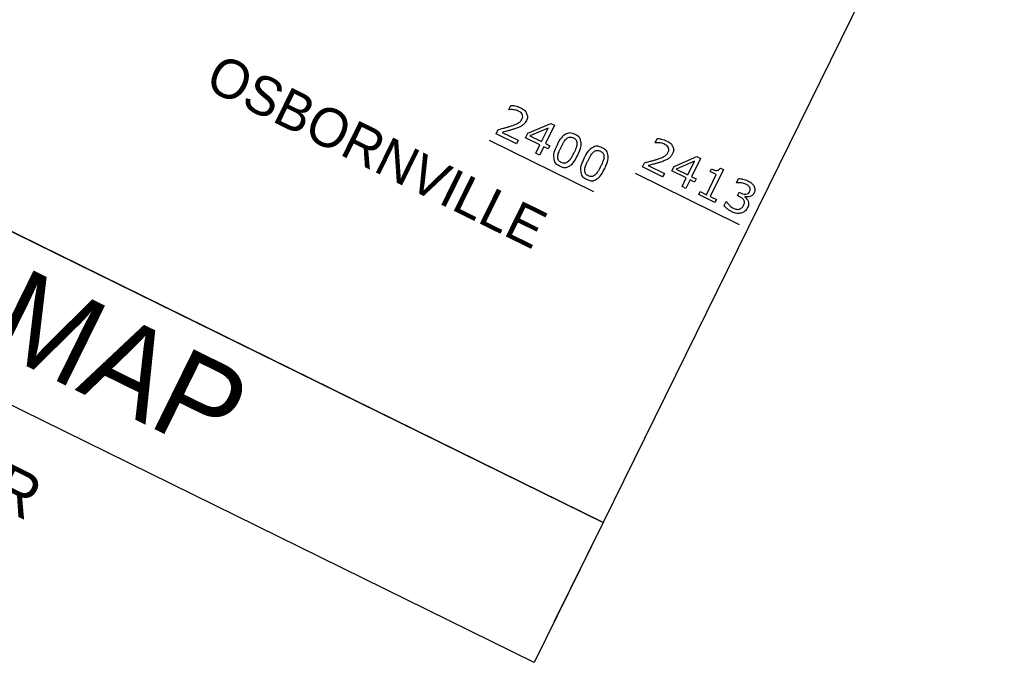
# Model space of a CAD drawing. Extents: x 1428128 to 1430390, y 857947 to 859822.
# Drawn here: x 1429086 to 1429305.6, y 859073.3 to 859217.9 of the extents above; entities that cross this region are included whole.
import ezdxf

# ---------------------------------------------------------------- set-up
doc = ezdxf.new("R2010")
doc.units = 0
for name, color, linetype in [('Old_Level_1', 7, 'Continuous'), ('Sheet Data Field CELL', 7, 'Continuous'), ('Sheet Title CELL', 7, 'Continuous')]:
    doc.layers.add(name, color=color, linetype=linetype)

msp = doc.modelspace()

# ---------------------------------------------------------------- linework, layer by layer
at = {"layer": 'Old_Level_1'}
for p, q in [((1429191.52, 859190.73), (1429214.98, 859179.19)), ((1429224.37, 859183.28), (1429247.75, 859171.78))]:
    msp.add_line(p, q, dxfattribs=at)
for points in [[(1429196.04, 859197.57), (1429196, 859197.59), (1429196.46, 859198.54)], [(1429204.83, 859188.76), (1429203.83, 859189.26), (1429202.9, 859187.36), (1429202.03, 859187.79), (1429202.96, 859189.68), (1429199.74, 859191.27), (1429200.25, 859192.31), (1429205.38, 859194.5), (1429206.21, 859194.09), (1429204.19, 859189.98), (1429205.19, 859189.49), (1429204.83, 859188.76)], [(1429203.32, 859190.41), (1429204.82, 859193.45), (1429200.71, 859191.69), (1429203.32, 859190.41)], [(1429197.68, 859189.93), (1429193.12, 859192.17), (1429193.59, 859193.12)], [(1429194.44, 859192.49), (1429198.07, 859190.71), (1429197.68, 859189.93)], [(1429228.9, 859190.12), (1429228.85, 859190.14), (1429229.32, 859191.09)], [(1429237.69, 859181.31), (1429236.69, 859181.8), (1429235.76, 859179.9), (1429234.89, 859180.33), (1429235.82, 859182.23), (1429232.6, 859183.81), (1429233.11, 859184.85), (1429238.24, 859187.04), (1429239.07, 859186.63), (1429237.05, 859182.52), (1429238.05, 859182.03), (1429237.69, 859181.31)], [(1429230.54, 859182.47), (1429225.98, 859184.71), (1429226.45, 859185.67)], [(1429227.3, 859185.03), (1429230.92, 859183.25), (1429230.54, 859182.47)], [(1429236.18, 859182.95), (1429237.67, 859185.99), (1429233.57, 859184.24), (1429236.18, 859182.95)], [(1429243.53, 859184.47), (1429244.23, 859184.12), (1429241.25, 859178.06), (1429242.62, 859177.38), (1429242.28, 859176.69)], [(1429242.28, 859176.69), (1429238.64, 859178.49), (1429238.98, 859179.17), (1429240.38, 859178.48), (1429242.6, 859182.99), (1429241.2, 859183.68), (1429241.5, 859184.3)], [(1429247.14, 859181.14), (1429247.1, 859181.16), (1429247.56, 859182.1)], [(1429247.77, 859178.07), (1429247.37, 859178.27), (1429247.73, 859179.01), (1429248.05, 859178.86)], [(1429249, 859178.04), (1429248.97, 859177.97)], [(1429244.34, 859176.03), (1429244.8, 859176.98), (1429244.87, 859176.94)]]:
    msp.add_lwpolyline(points, dxfattribs=at)
for points in [[(1429193.59, 859193.12), (1429194.27, 859193.29), (1429194.95, 859193.47), (1429195.62, 859193.64), (1429196.23, 859193.84), (1429197.52, 859194.25), (1429198.08, 859194.59), (1429198.65, 859194.92), (1429198.93, 859195.5), (1429199.19, 859196.02), (1429198.99, 859196.49), (1429198.78, 859196.95), (1429198.16, 859197.26), (1429197.75, 859197.46), (1429197.2, 859197.55), (1429196.65, 859197.64), (1429196.04, 859197.57)], [(1429196.46, 859198.54), (1429196.86, 859198.54), (1429197.46, 859198.41), (1429198.06, 859198.28), (1429198.57, 859198.03), (1429199.6, 859197.52), (1429199.95, 859196.73), (1429200.29, 859195.94), (1429199.87, 859195.09), (1429199.68, 859194.7), (1429199.42, 859194.42), (1429199.16, 859194.14), (1429198.82, 859193.93), (1429198.51, 859193.74), (1429198.14, 859193.58), (1429197.77, 859193.43), (1429197.26, 859193.27), (1429196.55, 859193.03), (1429195.81, 859192.84), (1429195.08, 859192.65), (1429194.44, 859192.49)], [(1429211.46, 859187.34), (1429210.56, 859185.52), (1429209.58, 859184.95), (1429208.59, 859184.38), (1429207.4, 859184.97), (1429206.19, 859185.56), (1429206.06, 859186.7), (1429205.92, 859187.83), (1429206.8, 859189.62), (1429207.68, 859191.41), (1429208.67, 859191.99), (1429209.66, 859192.57), (1429210.85, 859191.98), (1429212.06, 859191.39), (1429212.19, 859190.24), (1429212.32, 859189.1), (1429211.46, 859187.34)], [(1429209.26, 859185.87), (1429209.6, 859186.15), (1429209.9, 859186.62), (1429210.2, 859187.09), (1429210.54, 859187.79), (1429210.88, 859188.47), (1429211.07, 859189.01), (1429211.26, 859189.54), (1429211.27, 859189.98), (1429211.29, 859190.4), (1429211.1, 859190.71), (1429210.91, 859191.02), (1429210.49, 859191.24), (1429210.06, 859191.44), (1429209.7, 859191.4), (1429209.33, 859191.37), (1429208.99, 859191.09), (1429208.67, 859190.83), (1429208.35, 859190.32), (1429208.03, 859189.81), (1429207.72, 859189.16), (1429207.37, 859188.46), (1429207.18, 859187.96), (1429207, 859187.46), (1429206.98, 859187), (1429206.95, 859186.58), (1429207.14, 859186.26), (1429207.32, 859185.94), (1429207.77, 859185.71), (1429208.19, 859185.51), (1429208.56, 859185.54), (1429208.93, 859185.58), (1429209.26, 859185.87)], [(1429229.32, 859191.09), (1429229.72, 859191.09), (1429230.32, 859190.95), (1429230.92, 859190.82), (1429231.42, 859190.57), (1429232.46, 859190.06), (1429232.8, 859189.27), (1429233.15, 859188.49), (1429232.73, 859187.63), (1429232.54, 859187.25), (1429232.28, 859186.96), (1429232.02, 859186.68), (1429231.68, 859186.48), (1429231.37, 859186.28), (1429230.99, 859186.13), (1429230.62, 859185.97), (1429230.12, 859185.81), (1429229.4, 859185.58), (1429228.67, 859185.38), (1429227.94, 859185.19), (1429227.3, 859185.03)], [(1429217.52, 859184.35), (1429216.63, 859182.54), (1429215.64, 859181.97), (1429214.66, 859181.4), (1429213.46, 859181.98), (1429212.25, 859182.58), (1429212.12, 859183.71), (1429211.98, 859184.85), (1429212.86, 859186.63), (1429213.75, 859188.43), (1429214.73, 859189.01), (1429215.72, 859189.59), (1429216.92, 859189), (1429218.13, 859188.4), (1429218.26, 859187.26), (1429218.39, 859186.11), (1429217.52, 859184.35)], [(1429226.45, 859185.67), (1429227.13, 859185.84), (1429227.8, 859186.01), (1429228.48, 859186.18), (1429229.09, 859186.38), (1429230.37, 859186.79), (1429230.94, 859187.13), (1429231.5, 859187.47), (1429231.79, 859188.04), (1429232.04, 859188.56), (1429231.84, 859189.03), (1429231.64, 859189.5), (1429231.02, 859189.8), (1429230.61, 859190.01), (1429230.06, 859190.1), (1429229.5, 859190.19), (1429228.9, 859190.12)], [(1429215.32, 859182.88), (1429215.66, 859183.17), (1429215.96, 859183.64), (1429216.26, 859184.11), (1429216.6, 859184.8), (1429216.94, 859185.49), (1429217.13, 859186.03), (1429217.33, 859186.56), (1429217.34, 859186.99), (1429217.35, 859187.42), (1429217.16, 859187.73), (1429216.98, 859188.04), (1429216.55, 859188.25), (1429216.12, 859188.46), (1429215.76, 859188.42), (1429215.39, 859188.38), (1429215.06, 859188.1), (1429214.74, 859187.84), (1429214.42, 859187.33), (1429214.09, 859186.82), (1429213.78, 859186.18), (1429213.43, 859185.47), (1429213.25, 859184.98), (1429213.06, 859184.48), (1429213.04, 859184.02), (1429213.02, 859183.59), (1429213.2, 859183.27), (1429213.38, 859182.95), (1429213.83, 859182.73), (1429214.26, 859182.52), (1429214.62, 859182.56), (1429214.99, 859182.6), (1429215.32, 859182.88)], [(1429241.5, 859184.3), (1429241.78, 859184.16), (1429242.13, 859184.04), (1429242.48, 859183.93), (1429242.69, 859183.94), (1429242.96, 859183.95), (1429243.16, 859184.07), (1429243.37, 859184.18), (1429243.53, 859184.47)], [(1429248.05, 859178.86), (1429248.74, 859178.52), (1429249.29, 859178.6), (1429249.84, 859178.69), (1429250.11, 859179.24), (1429250.23, 859179.49), (1429250.22, 859179.72), (1429250.21, 859179.96), (1429250.08, 859180.17), (1429249.94, 859180.38), (1429249.74, 859180.53), (1429249.54, 859180.69), (1429249.26, 859180.83), (1429248.83, 859181.04), (1429248.27, 859181.12), (1429247.71, 859181.21), (1429247.14, 859181.14)], [(1429247.56, 859182.1), (1429247.96, 859182.1), (1429248.56, 859181.97), (1429249.17, 859181.84), (1429249.67, 859181.6), (1429250.16, 859181.35), (1429250.49, 859181.08), (1429250.82, 859180.8), (1429251.03, 859180.45), (1429251.25, 859180.08), (1429251.26, 859179.69), (1429251.28, 859179.3), (1429251.08, 859178.89), (1429250.8, 859178.33), (1429250.2, 859178.1), (1429249.6, 859177.88), (1429249, 859178.04)], [(1429244.87, 859176.94), (1429245.13, 859176.5), (1429245.57, 859176.08), (1429246, 859175.65), (1429246.49, 859175.42), (1429246.77, 859175.28), (1429247.14, 859175.21), (1429247.51, 859175.15), (1429247.8, 859175.24), (1429248.11, 859175.33), (1429248.33, 859175.52), (1429248.55, 859175.71), (1429248.73, 859176.08), (1429248.91, 859176.44), (1429248.91, 859176.74), (1429248.91, 859177.03), (1429248.77, 859177.27), (1429248.64, 859177.51), (1429248.37, 859177.71), (1429248.11, 859177.9), (1429247.77, 859178.07)], [(1429248.97, 859177.97), (1429249.17, 859177.83), (1429249.4, 859177.58), (1429249.62, 859177.32), (1429249.73, 859177.06)], [(1429249.73, 859177.06), (1429249.85, 859176.75), (1429249.85, 859176.39), (1429249.84, 859176.03), (1429249.61, 859175.56), (1429249.38, 859175.1), (1429249.03, 859174.8), (1429248.67, 859174.5), (1429248.23, 859174.36), (1429247.73, 859174.21), (1429247.2, 859174.28), (1429246.67, 859174.36), (1429246.12, 859174.63), (1429245.56, 859174.9), (1429245.08, 859175.3), (1429244.61, 859175.7), (1429244.34, 859176.03)]]:
    msp.add_open_spline(points, degree=3, dxfattribs=at)
at = {"layer": 'Sheet Title CELL'}
for p, q in [((1429358.43, 859391.92), (1429217.15, 859104.79)), ((1429217.15, 859104.79), (1428939, 859241.66)), ((1429217.15, 859104.79), (1429206.11, 859082.36))]:
    msp.add_line(p, q, dxfattribs=at)
msp.add_lwpolyline([(1428939, 859241.66), (1429217.15, 859104.79), (1429201.66, 859073.32), (1428923.51, 859210.19)], close=True, dxfattribs=at)

# ---------------------------------------------------------------- texts
at = {"layer": 'Old_Level_1'}
msp.add_text('OSBORNVILLE', height=8.75, rotation=333.8001, dxfattribs=at).set_placement((1429127.33, 859202.54))
at = {"layer": 'Sheet Data Field CELL'}
for s, height, p in [('VICINITY MAP', 20, (1428970.38, 859197.6)), ('OFFSITE DETOUR', 10, (1428982.96, 859156.62))]:
    msp.add_text(s, height=height, rotation=333.8001, dxfattribs=at).set_placement(p)

doc.saveas('drawing.dxf')
